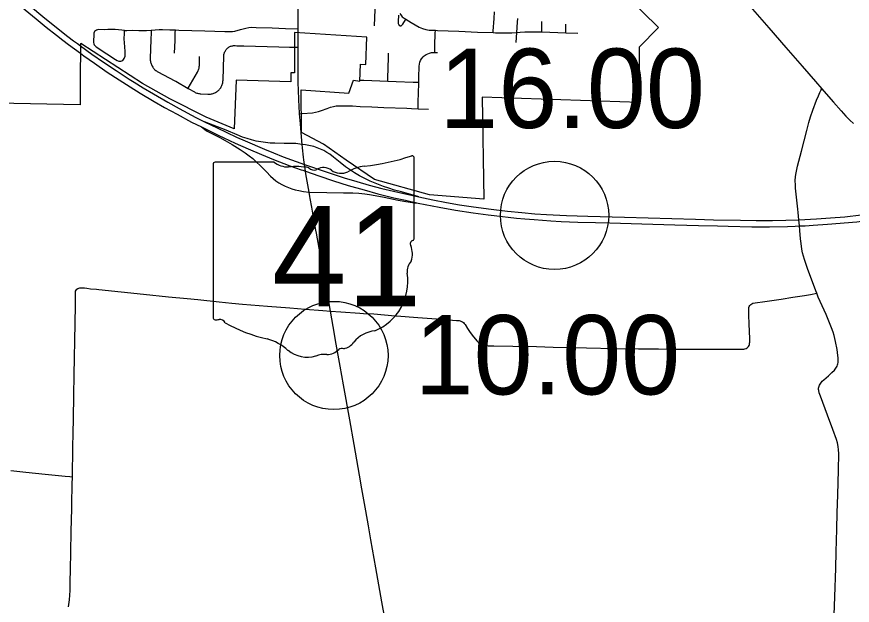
# Model space of a CAD drawing. Extents: x 1597222 to 1925846, y 496284 to 911751.
# Drawn here: x 1698562 to 1710137, y 546977 to 555136 of the extents above; entities that cross this region are included whole.
import ezdxf

# ---------------------------------------------------------------- set-up
doc = ezdxf.new("R2010")
doc.units = 0
for name, color, linetype in [('Default', 7, 'Continuous'), ('GM_X_City_Street', 7, 'Continuous'), ('GM_X_Corporation', 7, 'Continuous'), ('GM_X_County_Road', 7, 'Continuous'), ('GM_X_Interchange_Ramps', 7, 'Continuous'), ('GM_X_State_Route', 7, 'Continuous'), ('GM_X_State_Shield', 7, 'Continuous'), ('GM_X_Township_Road', 7, 'Continuous'), ('GM_X_US_Route', 7, 'Continuous')]:
    doc.layers.add(name, color=color, linetype=linetype)

msp = doc.modelspace()

# ---------------------------------------------------------------- linework, layer by layer
at = {"layer": 'Default'}
for centre in [(1706012, 552382), (1706012, 552382), (1702955, 550440), (1702955, 550440)]:
    msp.add_circle(centre, 750, dxfattribs=at)
at = {"layer": 'GM_X_City_Street'}
for points in [[(1703518, 555011), (1703525, 555237), (1703535, 555512), (1703536, 555549)], [(1703852, 555157), (1703848, 555068), (1703847, 555051), (1703848, 555042), (1703850, 555034), (1703853, 555026), (1703855, 555022), (1703857, 555019), (1703861, 555016), (1703864, 555014), (1703867, 555012), (1703871, 555010), (1703875, 555010), (1703880, 555010), (1703884, 555010), (1703888, 555012), (1703892, 555013), (1703895, 555015), (1703898, 555018), (1703901, 555021), (1703912, 555034), (1703923, 555053), (1703942, 555082), (1703954, 555100)], [(1703871, 555180), (1703883, 555161), (1703903, 555136), (1703928, 555116), (1703954, 555100)], [(1705163, 554915), (1705164, 554934), (1705175, 555112), (1705182, 555203)], [(1703954, 555100), (1704025, 555056), (1704139, 554992), (1704183, 554971), (1704229, 554957), (1704277, 554949), (1704361, 554947)], [(1705490, 554917), (1705499, 555062), (1705502, 555112)], [(1705834, 554924), (1705834, 554946), (1705835, 555010), (1705835, 555070)], [(1700057, 554945), (1700020, 554947), (1699926, 554958), (1699870, 554960), (1699824, 554957), (1699779, 554955), (1699700, 554956), (1699680, 554954), (1699665, 554948), (1699651, 554940), (1699641, 554931), (1699635, 554919), (1699631, 554907), (1699628, 554878), (1699624, 554799), (1699625, 554776), (1699629, 554760), (1699636, 554745), (1699647, 554733), (1699662, 554720), (1699810, 554622), (1699929, 554541), (1699955, 554527), (1699974, 554520), (1699990, 554518), (1700006, 554520), (1700019, 554524), (1700030, 554530), (1700042, 554541), (1700052, 554554), (1700057, 554566), (1700062, 554588), (1700065, 554614), (1700064, 554660), (1700060, 554713), (1700054, 554778), (1700052, 554824), (1700055, 554909), (1700057, 554945)], [(1700057, 554945), (1700089, 554946), (1700171, 554947), (1700255, 554945)], [(1700255, 554945), (1700301, 554944), (1700360, 554945), (1700426, 554950)], [(1700426, 554950), (1700424, 554914), (1700420, 554818), (1700411, 554555), (1700411, 554543), (1700412, 554531), (1700414, 554518), (1700416, 554506), (1700419, 554494), (1700423, 554482), (1700427, 554471), (1700432, 554459), (1700438, 554448), (1700445, 554438), (1700452, 554428), (1700460, 554418), (1700468, 554409), (1700477, 554400), (1700487, 554392), (1700497, 554385), (1700507, 554378), (1700518, 554372), (1700750, 554249), (1700765, 554241), (1700937, 554142)], [(1700426, 554950), (1700536, 554958), (1700582, 554959), (1700684, 554955), (1700759, 554952)], [(1700748, 554632), (1700755, 554805), (1700758, 554913), (1700759, 554952)], [(1700759, 554952), (1700808, 554951), (1701166, 554939), (1701444, 554929), (1701519, 554929), (1701552, 554931), (1701584, 554937), (1701660, 554957), (1701737, 554977), (1701778, 554985), (1701818, 554989), (1701880, 554988), (1702099, 554981), (1702286, 554974), (1702460, 554968)], [(1704352, 554640), (1704353, 554677), (1704354, 554740), (1704360, 554905), (1704361, 554947)], [(1704361, 554947), (1704392, 554946), (1704686, 554934), (1704946, 554923), (1705163, 554915)], [(1705163, 554915), (1705192, 554914), (1705338, 554910), (1705420, 554911), (1705490, 554917)], [(1705482, 554778), (1705490, 554917)], [(1705490, 554917), (1705536, 554921), (1705599, 554926), (1705714, 554926), (1705834, 554924)], [(1705834, 554924), (1706168, 554913)], [(1706168, 554913), (1706167, 554938), (1706168, 554975), (1706168, 555012), (1706168, 555030)], [(1706168, 554913), (1706334, 554906)], [(1700937, 554142), (1701024, 554092), (1701034, 554087), (1701045, 554082), (1701056, 554078), (1701067, 554074), (1701079, 554071), (1701091, 554069), (1701102, 554067), (1701114, 554066), (1701211, 554062), (1701223, 554061), (1701235, 554062), (1701247, 554063), (1701259, 554065), (1701271, 554068), (1701283, 554072), (1701294, 554076), (1701305, 554081), (1701316, 554086), (1701327, 554092), (1701337, 554099), (1701346, 554107), (1701356, 554115), (1701364, 554123), (1701372, 554132), (1701380, 554142), (1701387, 554152), (1701393, 554162), (1701399, 554173), (1701404, 554184), (1701409, 554195), (1701412, 554207), (1701415, 554219), (1701417, 554230), (1701419, 554243), (1701420, 554255), (1701431, 554592), (1701432, 554603), (1701433, 554613), (1701436, 554624), (1701439, 554634), (1701442, 554644), (1701447, 554654), (1701452, 554663), (1701458, 554672), (1701464, 554681), (1701471, 554689), (1701479, 554696), (1701487, 554703), (1701495, 554710), (1701504, 554716), (1701514, 554721), (1701523, 554725), (1701533, 554729), (1701544, 554732), (1701554, 554734), (1701565, 554736), (1701577, 554737), (1701587, 554736), (1701613, 554734), (1701706, 554731), (1702195, 554716), (1702342, 554714), (1702443, 554712), (1702460, 554712)], [(1700937, 554142), (1700939, 554145), (1701066, 554366), (1701071, 554377), (1701076, 554388), (1701081, 554399), (1701084, 554411), (1701087, 554423), (1701090, 554435), (1701091, 554447), (1701092, 554459), (1701096, 554585)], [(1703701, 554242), (1703703, 554284), (1703712, 554572), (1703713, 554618), (1703713, 554631)], [(1704131, 554228), (1704134, 554326), (1704135, 554418), (1704136, 554451), (1704140, 554480), (1704147, 554506), (1704157, 554530), (1704171, 554552), (1704191, 554578), (1704208, 554593), (1704235, 554612), (1704255, 554623), (1704280, 554632), (1704309, 554638), (1704338, 554640), (1704352, 554640)], [(1704352, 554640), (1704391, 554638)], [(1703314, 554257), (1703372, 554255), (1703482, 554250), (1703701, 554242)], [(1703701, 554242), (1703819, 554238), (1704055, 554230), (1704131, 554228)], [(1704122, 553860), (1704122, 553883), (1704124, 553952), (1704130, 554212), (1704131, 554228)], [(1702480, 553789), (1702514, 553792), (1702658, 553804), (1702700, 553811), (1702742, 553820), (1702783, 553834), (1702863, 553865), (1702909, 553881), (1702949, 553893), (1702988, 553899), (1703027, 553902), (1703105, 553902), (1703213, 553898), (1703321, 553893), (1703482, 553885), (1703649, 553879), (1703966, 553867), (1704031, 553864), (1704122, 553860)], [(1704122, 553860), (1704266, 553853)]]:
    msp.add_lwpolyline(points, dxfattribs=at)
at = {"layer": 'GM_X_Corporation'}
msp.add_lwpolyline([(1705466, 556934), (1707452, 554984), (1707184, 554712), (1707190, 553948), (1705011, 554019), (1705031, 552605), (1704278, 552665), (1703518, 552881), (1703124, 553145), (1702812, 553369), (1702507, 553529), (1702500, 554122), (1703161, 554076), (1703226, 554256), (1703313, 554240), (1703322, 554476), (1703396, 554473), (1703410, 554853), (1702409, 554915), (1702408, 554356), (1702358, 554359), (1702358, 554232), (1701600, 554258), (1701576, 553583), (1701186, 553743), (1700685, 553997), (1700305, 554210), (1699449, 554765), (1699444, 554760), (1699442, 554245), (1699439, 553916), (1698284, 553936)], dxfattribs=at)
at = {"layer": 'GM_X_County_Road'}
for points in [[(1706951, 557318), (1707186, 557048), (1707379, 556825), (1707497, 556689), (1707712, 556441), (1707895, 556231), (1708002, 556107), (1708132, 555960), (1708379, 555675), (1708561, 555464), (1708723, 555279), (1708820, 555167), (1708981, 554981), (1709216, 554709), (1709443, 554450), (1709625, 554239), (1709713, 554137)], [(1709387, 552422), (1709383, 552466), (1709360, 552678), (1709352, 552760), (1709349, 552792), (1709347, 552874), (1709348, 552906), (1709350, 552922), (1709359, 552971), (1709380, 553066), (1709432, 553273), (1709505, 553559), (1709534, 553670), (1709558, 553749), (1709590, 553841), (1709643, 553979), (1709667, 554040), (1709686, 554085), (1709701, 554113), (1709713, 554137)], [(1709713, 554137), (1709743, 554102), (1709875, 553952), (1709981, 553831), (1710047, 553759), (1710105, 553701), (1710153, 553656)], [(1709421, 552059), (1709410, 552172), (1709404, 552235), (1709396, 552320), (1709387, 552422)], [(1709644, 551303), (1709630, 551338), (1709517, 551646), (1709474, 551769), (1709460, 551816), (1709448, 551864), (1709439, 551912), (1709428, 551993), (1709421, 552059)], [(1709883, 546720), (1709897, 547097), (1709908, 547490), (1709914, 547720), (1709922, 548031), (1709928, 548261), (1709936, 548507), (1709947, 548851), (1709949, 549081), (1709947, 549131), (1709942, 549180), (1709931, 549228), (1709917, 549276), (1709868, 549415), (1709794, 549615), (1709696, 549876), (1709680, 549923), (1709673, 549954), (1709671, 549970), (1709671, 549986), (1709673, 550001), (1709677, 550016), (1709682, 550030), (1709690, 550044), (1709699, 550057), (1709709, 550070), (1709720, 550082), (1709744, 550104), (1709805, 550159), (1709854, 550203), (1709889, 550238), (1709909, 550265), (1709919, 550279), (1709926, 550294), (1709932, 550309), (1709937, 550325), (1709940, 550341), (1709942, 550358), (1709943, 550375), (1709942, 550408), (1709938, 550441), (1709925, 550522), (1709903, 550635), (1709885, 550715), (1709871, 550763), (1709849, 550825), (1709813, 550917), (1709774, 551007), (1709720, 551127), (1709666, 551246), (1709644, 551303)]]:
    msp.add_lwpolyline(points, dxfattribs=at)
at = {"layer": 'GM_X_Interchange_Ramps'}
for points in [[(1702515, 553366), (1702484, 553370), (1702457, 553373), (1702426, 553376), (1702364, 553378), (1702267, 553378), (1702136, 553381), (1702071, 553384), (1702007, 553391), (1701942, 553400), (1701878, 553412), (1701815, 553428), (1701752, 553447), (1701691, 553468), (1701615, 553498), (1701465, 553563), (1701161, 553680)], [(1701121, 553607), (1701169, 553571), (1701200, 553551), (1701375, 553461), (1701447, 553421), (1701547, 553363), (1701659, 553293), (1701727, 553248), (1701780, 553209), (1701831, 553168), (1701881, 553124), (1701941, 553068), (1702021, 552985), (1702078, 552926), (1702115, 552892), (1702153, 552861), (1702193, 552833), (1702236, 552808), (1702280, 552785), (1702325, 552766), (1702372, 552750), (1702419, 552737), (1702468, 552726), (1702533, 552715), (1702611, 552702)], [(1704131, 552639), (1703892, 552708), (1703797, 552733), (1703718, 552757), (1703641, 552784), (1703548, 552819), (1703458, 552857), (1703383, 552892), (1703311, 552930), (1703240, 552972), (1703171, 553017), (1703118, 553055), (1703041, 553116), (1702951, 553189), (1702898, 553228), (1702857, 553254), (1702814, 553279), (1702770, 553301), (1702725, 553319), (1702678, 553335), (1702656, 553341), (1702631, 553347), (1702608, 553351), (1702584, 553355), (1702564, 553359), (1702515, 553366)], [(1702611, 552702), (1702856, 552699), (1703087, 552695), (1703218, 552693), (1703301, 552689), (1703382, 552681), (1703448, 552672), (1703526, 552659), (1703654, 552636), (1703848, 552594), (1703951, 552574), (1704010, 552564), (1704073, 552555), (1704124, 552551)]]:
    msp.add_lwpolyline(points, dxfattribs=at)
at = {"layer": 'GM_X_State_Route'}
for points in [[(1702460, 554914), (1702460, 554968), (1702461, 555032), (1702460, 555175), (1702460, 555296), (1702460, 555314), (1702460, 555472)], [(1702461, 554321), (1702461, 554447), (1702459, 554663), (1702459, 554686), (1702460, 554712), (1702461, 554861), (1702460, 554914)], [(1702462, 554231), (1702461, 554321)], [(1702502, 553526), (1702501, 553531), (1702491, 553650), (1702480, 553789), (1702479, 553799), (1702470, 553982), (1702465, 554123), (1702462, 554214), (1702462, 554231)], [(1702536, 553188), (1702521, 553317), (1702515, 553366), (1702502, 553526)], [(1702577, 552905), (1702568, 552956), (1702564, 552995), (1702550, 553086), (1702540, 553151), (1702536, 553188)], [(1702621, 552644), (1702611, 552702), (1702577, 552905)], [(1702648, 552494), (1702626, 552614), (1702621, 552644)], [(1703329, 548676), (1703236, 549208), (1703175, 549548), (1703088, 550032), (1703043, 550291), (1702988, 550598), (1702945, 550840), (1702908, 551056), (1702879, 551216), (1702822, 551539), (1702714, 552136), (1702706, 552176), (1702690, 552255), (1702667, 552386), (1702648, 552494)], [(1703692, 546623), (1703620, 547026), (1703535, 547495), (1703468, 547883), (1703433, 548077), (1703397, 548287), (1703334, 548642), (1703329, 548676)]]:
    msp.add_lwpolyline(points, dxfattribs=at)
at = {"layer": 'GM_X_State_Shield'}
for p, q in [((1701284, 553085), (1701284, 550971)), ((1702126, 553121), (1701311, 553121)), ((1704068, 552068), (1704068, 553173)), ((1704068, 552068), (1704068, 552068))]:
    msp.add_line(p, q, dxfattribs=at)
for centre, radius, start, end in [((1703076, 556002), 2953, 275.8445, 288.9065), ((1704037, 553178), 31, 351.8621, 97.738), ((1701315, 553089), 32.3, 98.1301, 188.1301), ((1702321, 553366), 313, 231.6195, 271.1119), ((1703453, 552476), 594, 97.3462, 120.7689), ((1702424, 551935), 1123, 80.4867, 94.9883), ((1702679, 553100), 90.3, 219.7921, 297.1024), ((1702812, 552856), 188, 54.4667, 119.1411), ((1703054, 553191), 226, 233.8562, 294.8282), ((1704061, 551987), 48, 107.944, 210.337), ((1704035, 552064), 33.2, 289.6038, 7.7341), ((1703756, 551847), 288, 340.033, 23.6496), ((1704179, 551605), 210, 136.8065, 186.9296), ((1703241, 551465), 739, 292.3089, 8.9858), ((1701316, 550967), 32.5, 171.9584, 258.3066), ((1701321, 551183), 248, 267.339, 280.6039), ((1701371, 550850), 89.5, 29.7484, 93.2717), ((1702502, 552748), 2132, 240.4129, 257.1985), ((1703553, 550378), 404, 94.4031, 142.5768), ((1701866, 550022), 667, 47.1842, 75.836), ((1702863, 550681), 226, 268.777, 315.5493), ((1703067, 550476), 63.5, 65.7517, 132.6484), ((1703040, 550767), 239, 282.8732, 323.2771), ((1702588, 550839), 423, 230.7004, 286.2918), ((1702832, 550108), 348, 85.6951, 111.2099)]:
    msp.add_arc(centre, radius, start, end, dxfattribs=at)
at = {"layer": 'GM_X_Township_Road'}
for points in [[(1699333, 548760), (1699334, 548806), (1699335, 548856), (1699339, 549069), (1699340, 549167), (1699345, 549364), (1699348, 549561), (1699353, 549889), (1699359, 550168), (1699363, 550414), (1699367, 550643), (1699374, 551135), (1699375, 551184), (1699374, 551299), (1699375, 551316), (1699377, 551332), (1699384, 551347), (1699394, 551360), (1699407, 551369), (1699423, 551375), (1699437, 551378), (1699452, 551379), (1699471, 551378), (1699501, 551376), (1699533, 551372), (1699583, 551366), (1699666, 551357), (1699700, 551354), (1700320, 551291), (1700662, 551255), (1700923, 551228), (1701070, 551214), (1701364, 551183), (1701543, 551166), (1701691, 551153), (1702034, 551125), (1702344, 551099), (1702557, 551081), (1702802, 551063), (1702908, 551056)], [(1703806, 550991), (1703821, 550990), (1704116, 550967), (1704378, 550948), (1704541, 550935), (1704656, 550927), (1704689, 550923), (1704706, 550919), (1704722, 550913), (1704737, 550905), (1704750, 550895), (1704762, 550882), (1704772, 550869), (1704805, 550812), (1704833, 550771), (1704873, 550720), (1704936, 550645), (1704959, 550621), (1704971, 550611), (1704984, 550601), (1704997, 550593), (1705012, 550587), (1705027, 550582), (1705042, 550579), (1705058, 550577), (1705091, 550576), (1705173, 550575), (1705435, 550570), (1705764, 550563), (1705993, 550556), (1706453, 550547), (1706846, 550537), (1707175, 550533), (1707454, 550531), (1707650, 550528), (1707880, 550526), (1708323, 550528), (1708487, 550527), (1708602, 550527), (1708619, 550527), (1708634, 550529), (1708650, 550533), (1708665, 550538), (1708679, 550545), (1708690, 550555), (1708700, 550566), (1708707, 550580), (1708712, 550594), (1708715, 550610), (1708717, 550626), (1708717, 550675), (1708710, 550872), (1708705, 551003), (1708702, 551053), (1708702, 551086), (1708704, 551103), (1708710, 551119), (1708718, 551134), (1708730, 551146), (1708744, 551156), (1708760, 551163), (1708793, 551170), (1708923, 551188), (1709150, 551222), (1709313, 551247), (1709475, 551271), (1709556, 551283), (1709644, 551303)], [(1702908, 551056), (1703052, 551046), (1703314, 551028), (1703365, 551024)], [(1703365, 551024), (1703511, 551015), (1703806, 550991)], [(1698482, 548846), (1698646, 548829), (1698776, 548815), (1699004, 548792), (1699233, 548768), (1699298, 548762), (1699333, 548760)], [(1699280, 546956), (1699293, 547053), (1699299, 547118), (1699302, 547184), (1699303, 547299), (1699307, 547479), (1699313, 547708), (1699318, 548003), (1699324, 548315), (1699325, 548462), (1699328, 548575), (1699330, 548654), (1699333, 548760)]]:
    msp.add_lwpolyline(points, dxfattribs=at)
at = {"layer": 'GM_X_US_Route'}
for points in [[(1697598, 556276), (1697640, 556230), (1697797, 556062), (1697923, 555934), (1698063, 555795), (1698193, 555671), (1698349, 555525), (1698532, 555361), (1698680, 555231), (1698830, 555104), (1698969, 554990), (1699111, 554878), (1699202, 554810), (1699281, 554750), (1699444, 554631)], [(1698723, 555305), (1698950, 555116), (1699129, 554972), (1699206, 554912), (1699271, 554861), (1699350, 554802), (1699402, 554762), (1699444, 554732), (1699602, 554618), (1699764, 554507), (1699941, 554388), (1700120, 554272), (1700189, 554228), (1700315, 554150), (1700455, 554066), (1700654, 553951), (1700812, 553863), (1701044, 553740), (1701161, 553680), (1701337, 553594), (1701471, 553530), (1701605, 553468), (1701725, 553415), (1701996, 553299), (1702117, 553249), (1702255, 553194), (1702550, 553086), (1702848, 552984), (1703098, 552904), (1703271, 552852), (1703445, 552802), (1703619, 552756), (1703779, 552717), (1704131, 552639), (1704324, 552598), (1704517, 552561), (1704695, 552530), (1704890, 552501), (1705134, 552468), (1705362, 552440), (1705558, 552420), (1705737, 552405), (1705901, 552395), (1706180, 552381), (1706475, 552370), (1706983, 552356), (1707967, 552328), (1708213, 552322), (1708590, 552315), (1708804, 552311), (1709033, 552311), (1709214, 552314), (1709396, 552320), (1709640, 552333), (1709836, 552347), (1710032, 552364), (1710261, 552388)], [(1699444, 554631), (1699493, 554595), (1699640, 554490), (1699815, 554369), (1699979, 554260), (1700131, 554164), (1700271, 554078), (1700468, 553960), (1700610, 553879), (1700783, 553784), (1700985, 553676), (1701121, 553607), (1701215, 553565), (1701352, 553493), (1701590, 553382), (1701769, 553302), (1701951, 553226), (1702118, 553158), (1702347, 553069), (1702501, 553015), (1702523, 553008)], [(1702523, 553008), (1702564, 552995), (1702749, 552928), (1702952, 552861), (1703155, 552798), (1703376, 552734), (1703566, 552682), (1703788, 552626), (1703946, 552592), (1704020, 552576), (1704069, 552567), (1704124, 552551), (1704414, 552494), (1704640, 552456), (1704883, 552418), (1705094, 552388), (1705175, 552378), (1705485, 552344), (1705599, 552333), (1705730, 552323), (1705959, 552307), (1706106, 552298), (1706336, 552289), (1706581, 552283), (1706778, 552278), (1707221, 552266), (1707680, 552252), (1707844, 552247), (1708008, 552243), (1708270, 552236), (1708418, 552233), (1708746, 552224), (1708991, 552223), (1709237, 552229), (1709347, 552233)], [(1709347, 552233), (1709404, 552235), (1709483, 552239), (1709597, 552245), (1709794, 552259), (1710202, 552294), (1710332, 552309), (1710690, 552356), (1711026, 552406), (1711241, 552442), (1711565, 552492), (1712164, 552587), (1712231, 552597)]]:
    msp.add_lwpolyline(points, dxfattribs=at)

# ---------------------------------------------------------------- texts
at = {"layer": 'Default'}
for s, p in [('16.00', (1704415, 553593)), ('16.00', (1704415, 553593)), ('10.00', (1704073, 549900)), ('10.00', (1704073, 549900))]:
    msp.add_text(s, height=1100, dxfattribs=at).set_placement(p)
at = {"layer": 'GM_X_State_Shield'}
msp.add_text('41', height=1392.2, dxfattribs=at).set_placement((1702098, 551120))

doc.saveas('drawing.dxf')
